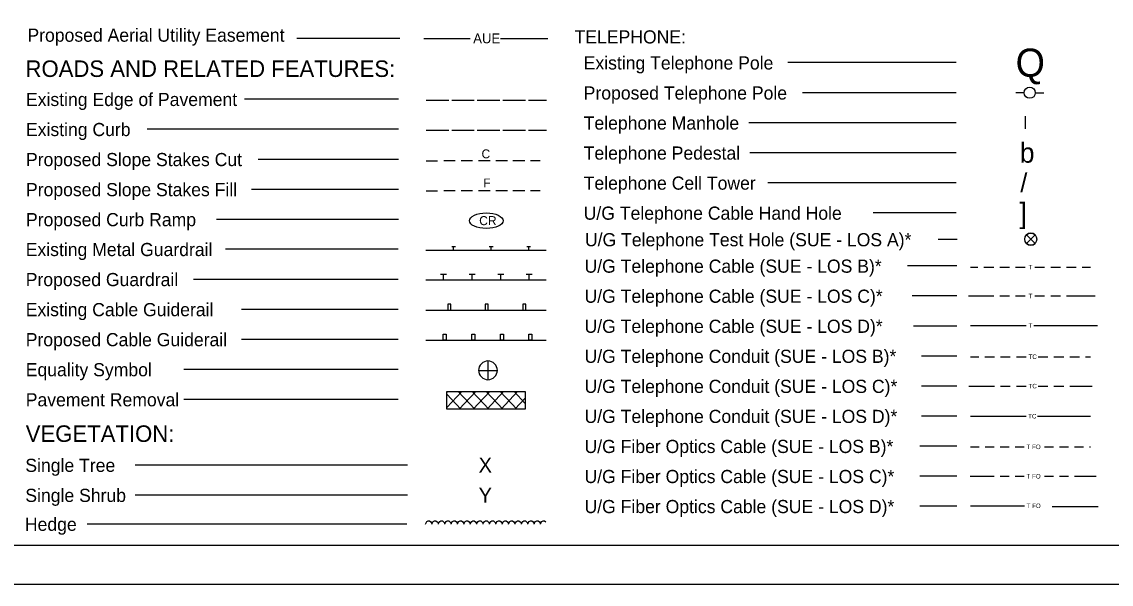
# Model space of a CAD drawing. Extents: x 885291.5 to 885334, y 651348 to 651383.7.
# Drawn here: x 885305.76 to 885323.88, y 651348.02 to 651357.38 of the extents above; entities that cross this region are included whole.
import ezdxf

# ---------------------------------------------------------------- set-up
doc = ezdxf.new("R2010")
doc.units = 0
for name, color, linetype in [('Default', 7, 'Continuous'), ('Prop WCC CELL', 7, 'Continuous'), ('Sheet Symbology CELL', 7, 'Continuous'), ('Stewart Plot Border Xerox6279 and LJ5000', 7, 'Continuous')]:
    doc.layers.add(name, color=color, linetype=linetype)

msp = doc.modelspace()

# ---------------------------------------------------------------- linework, layer by layer
at = {"layer": 'Default'}
for points in [[(885322.613, 651353.833), (885322.471, 651353.692), (885322.542, 651353.763), (885322.471, 651353.833), (885322.613, 651353.692)], [(885322.471, 651353.833), (885322.542, 651353.763), (885322.613, 651353.833)], [(885322.613, 651353.692), (885322.542, 651353.763), (885322.471, 651353.692)]]:
    msp.add_lwpolyline(points, dxfattribs=at)
msp.add_circle((885322.542, 651353.763), 0.0999, dxfattribs=at)
for start, end in [(45, 135), (225, 315)]:
    msp.add_arc((885322.542, 651353.763), 0.0999, start, end, dxfattribs=at)
at = {"layer": 'Prop WCC CELL'}
msp.add_ellipse((885313.486, 651354.07), major_axis=(0.28, 0), ratio=0.462467, dxfattribs=at)
at = {"layer": 'Sheet Symbology CELL'}
for p, q in [((885312.048, 651357.104), (885310.336, 651357.104)), ((885312.448, 651357.104), (885312.532, 651357.104)), ((885312.532, 651357.104), (885313.22, 651357.104)), ((885313.72, 651357.104), (885314.407, 651357.104)), ((885314.407, 651357.104), (885314.511, 651357.104)), ((885321.299, 651356.7), (885318.502, 651356.7)), ((885312.024, 651356.091), (885309.465, 651356.091)), ((885312.487, 651356.077), (885312.862, 651356.077)), ((885312.912, 651356.077), (885313.287, 651356.077)), ((885313.337, 651356.077), (885313.712, 651356.077)), ((885313.762, 651356.077), (885314.137, 651356.077)), ((885314.187, 651356.077), (885314.487, 651356.077)), ((885321.299, 651356.2), (885318.747, 651356.2)), ((885322.431, 651356.2), (885322.291, 651356.2)), ((885322.619, 651356.2), (885322.759, 651356.2)), ((885312.024, 651355.591), (885307.845, 651355.591)), ((885312.487, 651355.577), (885312.862, 651355.577)), ((885312.912, 651355.577), (885313.287, 651355.577)), ((885313.337, 651355.577), (885313.712, 651355.577)), ((885313.762, 651355.577), (885314.137, 651355.577)), ((885314.187, 651355.577), (885314.487, 651355.577)), ((885321.299, 651355.7), (885317.852, 651355.7)), ((885321.299, 651355.2), (885317.87, 651355.2)), ((885312.024, 651355.091), (885309.694, 651355.091)), ((885312.487, 651355.065), (885312.677, 651355.065)), ((885312.969, 651355.065), (885312.781, 651355.065)), ((885313.257, 651355.065), (885313.067, 651355.065)), ((885313.551, 651355.065), (885313.356, 651355.065)), ((885313.837, 651355.065), (885313.643, 651355.065)), ((885314.126, 651355.065), (885313.929, 651355.065)), ((885314.383, 651355.065), (885314.223, 651355.065)), ((885321.299, 651354.7), (885318.168, 651354.7)), ((885312.024, 651354.591), (885309.58, 651354.591)), ((885312.487, 651354.565), (885312.677, 651354.565)), ((885312.969, 651354.565), (885312.781, 651354.565)), ((885313.257, 651354.565), (885313.067, 651354.565)), ((885313.551, 651354.565), (885313.356, 651354.565)), ((885313.837, 651354.565), (885313.643, 651354.565)), ((885314.126, 651354.565), (885313.929, 651354.565)), ((885314.383, 651354.565), (885314.223, 651354.565)), ((885312.024, 651354.091), (885309, 651354.091)), ((885321.299, 651354.2), (885319.923, 651354.2)), ((885321.319, 651353.758), (885321.003, 651353.758)), ((885312.02, 651353.594), (885309.149, 651353.594)), ((885312.483, 651353.58), (885314.483, 651353.58)), ((885312.911, 651353.642), (885312.974, 651353.642)), ((885312.943, 651353.58), (885312.943, 651353.642)), ((885313.536, 651353.642), (885313.599, 651353.642)), ((885313.568, 651353.58), (885313.568, 651353.642)), ((885314.161, 651353.642), (885314.224, 651353.642)), ((885314.193, 651353.58), (885314.193, 651353.642)), ((885312.726, 651353.179), (885312.826, 651353.179)), ((885312.776, 651353.08), (885312.776, 651353.179)), ((885313.201, 651353.179), (885313.301, 651353.179)), ((885313.251, 651353.08), (885313.251, 651353.179)), ((885313.676, 651353.179), (885313.776, 651353.179)), ((885313.726, 651353.08), (885313.726, 651353.179)), ((885314.151, 651353.179), (885314.251, 651353.179)), ((885314.201, 651353.08), (885314.201, 651353.179)), ((885321.312, 651353.317), (885320.493, 651353.317)), ((885321.538, 651353.297), (885321.663, 651353.297)), ((885321.763, 651353.297), (885321.926, 651353.297)), ((885322.026, 651353.297), (885322.188, 651353.297)), ((885322.288, 651353.297), (885322.451, 651353.297)), ((885322.611, 651353.297), (885322.773, 651353.297)), ((885322.873, 651353.297), (885323.036, 651353.297)), ((885323.136, 651353.297), (885323.298, 651353.297)), ((885323.398, 651353.297), (885323.538, 651353.297)), ((885312.02, 651353.094), (885308.614, 651353.094)), ((885314.483, 651353.08), (885312.483, 651353.08)), ((885321.312, 651352.817), (885320.572, 651352.817)), ((885321.506, 651352.817), (885321.926, 651352.817)), ((885322.026, 651352.817), (885322.188, 651352.817)), ((885322.288, 651352.817), (885322.451, 651352.817)), ((885322.611, 651352.817), (885322.773, 651352.817)), ((885322.873, 651352.817), (885323.036, 651352.817)), ((885323.136, 651352.817), (885323.612, 651352.817)), ((885312.02, 651352.594), (885309.412, 651352.594)), ((885312.483, 651352.58), (885314.483, 651352.58)), ((885321.312, 651352.317), (885320.591, 651352.317)), ((885321.538, 651352.326), (885322.466, 651352.326)), ((885322.591, 651352.326), (885323.65, 651352.326)), ((885312.02, 651352.094), (885309.412, 651352.094)), ((885312.483, 651352.08), (885314.483, 651352.08)), ((885313.514, 651351.736), (885313.514, 651351.58)), ((885321.312, 651351.817), (885320.726, 651351.817)), ((885321.538, 651351.807), (885321.677, 651351.807)), ((885321.777, 651351.807), (885321.94, 651351.807)), ((885322.04, 651351.807), (885322.202, 651351.807)), ((885322.302, 651351.807), (885322.465, 651351.807)), ((885322.665, 651351.807), (885322.827, 651351.807)), ((885322.927, 651351.807), (885323.09, 651351.807)), ((885323.19, 651351.807), (885323.352, 651351.807)), ((885323.452, 651351.807), (885323.538, 651351.807)), ((885312.02, 651351.594), (885308.454, 651351.594)), ((885313.357, 651351.58), (885313.514, 651351.58)), ((885313.514, 651351.58), (885313.514, 651351.423)), ((885313.514, 651351.58), (885313.67, 651351.58)), ((885312.832, 651351.226), (885314.134, 651351.226)), ((885312.832, 651350.934), (885312.832, 651351.226)), ((885312.832, 651351.211), (885312.845, 651351.226)), ((885312.832, 651350.963), (885313.078, 651351.226)), ((885313.063, 651350.934), (885312.832, 651351.181)), ((885313.295, 651350.934), (885313.02, 651351.226)), ((885313.035, 651350.934), (885313.31, 651351.226)), ((885313.527, 651350.934), (885313.253, 651351.226)), ((885313.267, 651350.934), (885313.543, 651351.226)), ((885313.759, 651350.934), (885313.484, 651351.226)), ((885313.499, 651350.934), (885313.774, 651351.226)), ((885313.992, 651350.934), (885313.715, 651351.226)), ((885313.732, 651350.934), (885314.005, 651351.226)), ((885314.134, 651351.028), (885313.948, 651351.226)), ((885314.134, 651351.226), (885314.134, 651350.934)), ((885321.312, 651351.317), (885320.726, 651351.317)), ((885321.514, 651351.317), (885321.94, 651351.317)), ((885322.04, 651351.317), (885322.202, 651351.317)), ((885322.302, 651351.317), (885322.465, 651351.317)), ((885322.665, 651351.317), (885322.827, 651351.317)), ((885322.927, 651351.317), (885323.09, 651351.317)), ((885323.19, 651351.317), (885323.562, 651351.317)), ((885312.02, 651351.094), (885308.454, 651351.094)), ((885313.963, 651350.934), (885314.134, 651351.116)), ((885314.134, 651350.934), (885312.832, 651350.934)), ((885321.312, 651350.817), (885320.726, 651350.817)), ((885321.538, 651350.816), (885322.465, 651350.816)), ((885322.652, 651350.816), (885323.538, 651350.816)), ((885321.312, 651350.317), (885320.697, 651350.317)), ((885321.538, 651350.306), (885321.684, 651350.306)), ((885321.784, 651350.306), (885321.934, 651350.306)), ((885322.034, 651350.306), (885322.184, 651350.306)), ((885322.284, 651350.306), (885322.434, 651350.306)), ((885322.771, 651350.306), (885322.921, 651350.306)), ((885323.021, 651350.306), (885323.171, 651350.306)), ((885323.271, 651350.306), (885323.421, 651350.306)), ((885323.521, 651350.306), (885323.538, 651350.306)), ((885312.173, 651350.003), (885307.645, 651350.003)), ((885321.312, 651349.817), (885320.697, 651349.817)), ((885321.533, 651349.817), (885321.934, 651349.817)), ((885322.034, 651349.817), (885322.184, 651349.817)), ((885322.284, 651349.817), (885322.434, 651349.817)), ((885322.771, 651349.817), (885322.921, 651349.817)), ((885323.021, 651349.817), (885323.171, 651349.817)), ((885323.271, 651349.817), (885323.629, 651349.817)), ((885312.173, 651349.503), (885307.645, 651349.503)), ((885321.312, 651349.317), (885320.697, 651349.317)), ((885321.538, 651349.326), (885322.435, 651349.326)), ((885322.897, 651349.316), (885323.663, 651349.316)), ((885312.166, 651349.022), (885306.849, 651349.022)), ((885312.476, 651349.022), (885312.484, 651349.045)), ((885312.484, 651349.045), (885312.499, 651349.062)), ((885312.499, 651349.062), (885312.519, 651349.073)), ((885312.519, 651349.073), (885312.543, 651349.073)), ((885312.543, 651349.073), (885312.563, 651349.06)), ((885312.563, 651349.06), (885312.576, 651349.044)), ((885312.576, 651349.044), (885312.581, 651349.023)), ((885312.583, 651349.022), (885312.59, 651349.045)), ((885312.59, 651349.045), (885312.605, 651349.062)), ((885312.605, 651349.062), (885312.625, 651349.073)), ((885312.625, 651349.073), (885312.649, 651349.073)), ((885312.649, 651349.073), (885312.669, 651349.06)), ((885312.669, 651349.06), (885312.683, 651349.044)), ((885312.683, 651349.044), (885312.688, 651349.023)), ((885312.689, 651349.022), (885312.696, 651349.045)), ((885312.696, 651349.045), (885312.711, 651349.062)), ((885312.711, 651349.062), (885312.731, 651349.073)), ((885312.731, 651349.073), (885312.755, 651349.073)), ((885312.755, 651349.073), (885312.775, 651349.06)), ((885312.775, 651349.06), (885312.789, 651349.044)), ((885312.789, 651349.044), (885312.794, 651349.023)), ((885312.795, 651349.022), (885312.803, 651349.045)), ((885312.803, 651349.045), (885312.818, 651349.062)), ((885312.818, 651349.062), (885312.838, 651349.073)), ((885312.838, 651349.073), (885312.861, 651349.073)), ((885312.861, 651349.073), (885312.881, 651349.06)), ((885312.881, 651349.06), (885312.895, 651349.044)), ((885312.895, 651349.044), (885312.9, 651349.023)), ((885312.901, 651349.022), (885312.909, 651349.045)), ((885312.909, 651349.045), (885312.924, 651349.062)), ((885312.924, 651349.062), (885312.944, 651349.073)), ((885312.944, 651349.073), (885312.968, 651349.073)), ((885312.968, 651349.073), (885312.988, 651349.06)), ((885312.988, 651349.06), (885313.001, 651349.044)), ((885313.001, 651349.044), (885313.006, 651349.023)), ((885313.008, 651349.022), (885313.015, 651349.045)), ((885313.015, 651349.045), (885313.03, 651349.062)), ((885313.03, 651349.062), (885313.05, 651349.073)), ((885313.05, 651349.073), (885313.074, 651349.073)), ((885313.074, 651349.073), (885313.094, 651349.06)), ((885313.094, 651349.06), (885313.108, 651349.044)), ((885313.108, 651349.044), (885313.113, 651349.023)), ((885313.114, 651349.022), (885313.121, 651349.045)), ((885313.121, 651349.045), (885313.136, 651349.062)), ((885313.136, 651349.062), (885313.156, 651349.073)), ((885313.156, 651349.073), (885313.18, 651349.073)), ((885313.18, 651349.073), (885313.2, 651349.06)), ((885313.2, 651349.06), (885313.214, 651349.044)), ((885313.214, 651349.044), (885313.219, 651349.023)), ((885313.22, 651349.022), (885313.228, 651349.045)), ((885313.228, 651349.045), (885313.243, 651349.062)), ((885313.243, 651349.062), (885313.263, 651349.073)), ((885313.263, 651349.073), (885313.286, 651349.073)), ((885313.286, 651349.073), (885313.306, 651349.06)), ((885313.306, 651349.06), (885313.32, 651349.044)), ((885313.32, 651349.044), (885313.325, 651349.023)), ((885313.326, 651349.022), (885313.334, 651349.045)), ((885313.334, 651349.045), (885313.349, 651349.062)), ((885313.349, 651349.062), (885313.369, 651349.073)), ((885313.369, 651349.073), (885313.393, 651349.073)), ((885313.393, 651349.073), (885313.413, 651349.06)), ((885313.413, 651349.06), (885313.426, 651349.044)), ((885313.426, 651349.044), (885313.431, 651349.023)), ((885313.433, 651349.022), (885313.44, 651349.045)), ((885313.44, 651349.045), (885313.455, 651349.062)), ((885313.455, 651349.062), (885313.475, 651349.073)), ((885313.475, 651349.073), (885313.499, 651349.073)), ((885313.499, 651349.073), (885313.519, 651349.06)), ((885313.519, 651349.06), (885313.533, 651349.044)), ((885313.533, 651349.044), (885313.538, 651349.023)), ((885313.539, 651349.022), (885313.546, 651349.045)), ((885313.546, 651349.045), (885313.561, 651349.062)), ((885313.561, 651349.062), (885313.581, 651349.073)), ((885313.581, 651349.073), (885313.605, 651349.073)), ((885313.605, 651349.073), (885313.625, 651349.06)), ((885313.625, 651349.06), (885313.639, 651349.044)), ((885313.639, 651349.044), (885313.644, 651349.023)), ((885313.645, 651349.022), (885313.653, 651349.045)), ((885313.653, 651349.045), (885313.668, 651349.062)), ((885313.668, 651349.062), (885313.688, 651349.073)), ((885313.688, 651349.073), (885313.711, 651349.073)), ((885313.711, 651349.073), (885313.731, 651349.06)), ((885313.731, 651349.06), (885313.745, 651349.044)), ((885313.745, 651349.044), (885313.75, 651349.023)), ((885313.751, 651349.022), (885313.759, 651349.045)), ((885313.759, 651349.045), (885313.774, 651349.062)), ((885313.774, 651349.062), (885313.794, 651349.073)), ((885313.794, 651349.073), (885313.818, 651349.073)), ((885313.818, 651349.073), (885313.838, 651349.06)), ((885313.838, 651349.06), (885313.851, 651349.044)), ((885313.851, 651349.044), (885313.856, 651349.023)), ((885313.858, 651349.022), (885313.865, 651349.045)), ((885313.865, 651349.045), (885313.88, 651349.062)), ((885313.88, 651349.062), (885313.9, 651349.073)), ((885313.9, 651349.073), (885313.924, 651349.073)), ((885313.924, 651349.073), (885313.944, 651349.06)), ((885313.944, 651349.06), (885313.958, 651349.044)), ((885313.958, 651349.044), (885313.963, 651349.023)), ((885313.964, 651349.022), (885313.971, 651349.045)), ((885313.971, 651349.045), (885313.986, 651349.062)), ((885313.986, 651349.062), (885314.006, 651349.073)), ((885314.006, 651349.073), (885314.03, 651349.073)), ((885314.03, 651349.073), (885314.05, 651349.06)), ((885314.05, 651349.06), (885314.064, 651349.044)), ((885314.064, 651349.044), (885314.069, 651349.023)), ((885314.07, 651349.022), (885314.078, 651349.045)), ((885314.078, 651349.045), (885314.093, 651349.062)), ((885314.093, 651349.062), (885314.113, 651349.073)), ((885314.113, 651349.073), (885314.136, 651349.073)), ((885314.136, 651349.073), (885314.156, 651349.06)), ((885314.156, 651349.06), (885314.17, 651349.044)), ((885314.17, 651349.044), (885314.175, 651349.023)), ((885314.176, 651349.022), (885314.184, 651349.045)), ((885314.184, 651349.045), (885314.199, 651349.062)), ((885314.199, 651349.062), (885314.219, 651349.073)), ((885314.219, 651349.073), (885314.243, 651349.073)), ((885314.243, 651349.073), (885314.263, 651349.06)), ((885314.263, 651349.06), (885314.276, 651349.044)), ((885314.276, 651349.044), (885314.281, 651349.023)), ((885314.283, 651349.022), (885314.29, 651349.045)), ((885314.29, 651349.045), (885314.305, 651349.062)), ((885314.305, 651349.062), (885314.325, 651349.073)), ((885314.325, 651349.073), (885314.349, 651349.073)), ((885314.349, 651349.073), (885314.369, 651349.06)), ((885314.369, 651349.06), (885314.383, 651349.044)), ((885314.383, 651349.044), (885314.388, 651349.023)), ((885314.389, 651349.022), (885314.396, 651349.045)), ((885314.396, 651349.045), (885314.411, 651349.062)), ((885314.411, 651349.062), (885314.431, 651349.073)), ((885314.431, 651349.073), (885314.455, 651349.073)), ((885314.455, 651349.073), (885314.475, 651349.06)), ((885314.475, 651349.06), (885314.476, 651349.059))]:
    msp.add_line(p, q, dxfattribs=at)
for points in [[(885333.401, 651374.896), (885295.901, 651374.896), (885295.901, 651348.671), (885333.401, 651348.671)], [(885312.845, 651352.58), (885312.895, 651352.58), (885312.895, 651352.68), (885312.845, 651352.68)], [(885313.47, 651352.58), (885313.52, 651352.58), (885313.52, 651352.68), (885313.47, 651352.68)], [(885314.095, 651352.58), (885314.145, 651352.58), (885314.145, 651352.68), (885314.095, 651352.68)], [(885312.77, 651352.18), (885312.82, 651352.18), (885312.82, 651352.08), (885312.77, 651352.08)], [(885313.245, 651352.18), (885313.295, 651352.18), (885313.295, 651352.08), (885313.245, 651352.08)], [(885313.72, 651352.18), (885313.77, 651352.18), (885313.77, 651352.08), (885313.72, 651352.08)], [(885314.195, 651352.18), (885314.245, 651352.18), (885314.245, 651352.08), (885314.195, 651352.08)]]:
    msp.add_lwpolyline(points, close=True, dxfattribs=at)
msp.add_circle((885322.524, 651356.2), 0.0937, dxfattribs=at)
for start, end in [(89.9944, 179.9989), (359.9944, 89.9989), (179.9944, 269.9989), (269.9944, 359.9989)]:
    msp.add_arc((885313.514, 651351.58), 0.156, start, end, dxfattribs=at)
at = {"layer": 'Stewart Plot Border Xerox6279 and LJ5000'}
msp.add_lwpolyline([(885291.526, 651348.021), (885334.026, 651348.021), (885334.026, 651375.521), (885291.526, 651375.521)], close=True, dxfattribs=at)

# ---------------------------------------------------------------- texts
at = {"layer": 'Prop WCC CELL'}
msp.add_text('CR', height=0.15, dxfattribs=at).set_placement((885313.368, 651353.996))
at = {"layer": 'Sheet Symbology CELL'}
for s, height, p in [('Proposed Aerial Utility Easement', 0.21875, (885305.854, 651357.048)), ('AUE', 0.1637, (885313.268, 651357.022)), ('TELEPHONE:', 0.2188, (885314.954, 651357.019)), ('Existing Telephone Pole', 0.21875, (885315.106, 651356.586)), ('Q', 0.469, (885322.29, 651356.465)), ('ROADS AND RELATED FEATURES:', 0.275, (885305.822, 651356.462)), ('Proposed Telephone Pole', 0.21875, (885315.106, 651356.086)), ('Existing Edge of Pavement', 0.21875, (885305.83, 651355.978)), ('Telephone Manhole', 0.21875, (885315.106, 651355.586)), ('l', 0.206, (885322.421, 651355.597)), ('Existing Curb', 0.21875, (885305.83, 651355.478)), ('b', 0.33, (885322.359, 651355.035)), ('Proposed Slope Stakes Cut', 0.21875, (885305.83, 651354.978)), ('C', 0.148, (885313.407, 651355.108)), ('Telephone Pedestal', 0.21875, (885315.106, 651355.086)), ('Telephone Cell Tower', 0.21875, (885315.106, 651354.586)), ('/', 0.313, (885322.368, 651354.544)), ('Proposed Slope Stakes Fill', 0.21875, (885305.83, 651354.478)), ('F', 0.148, (885313.437, 651354.624)), ('U/G Telephone Cable Hand Hole', 0.21875, (885315.106, 651354.086)), (']', 0.337, (885322.355, 651354.031)), ('Proposed Curb Ramp', 0.21875, (885305.83, 651353.978)), ('U/G Telephone Test Hole (SUE - LOS A)*', 0.21875, (885315.127, 651353.644)), ('Existing Metal Guardrail', 0.21875, (885305.826, 651353.481)), ('U/G Telephone Cable (SUE - LOS B)*', 0.21875, (885315.12, 651353.204)), ('Proposed Guardrail', 0.21875, (885305.826, 651352.981)), ('T', 0.075, (885322.507, 651353.26)), ('U/G Telephone Cable (SUE - LOS C)*', 0.21875, (885315.12, 651352.704)), ('T', 0.075, (885322.507, 651352.78)), ('Existing Cable Guiderail', 0.21875, (885305.826, 651352.481)), ('U/G Telephone Cable (SUE - LOS D)*', 0.21875, (885315.12, 651352.204)), ('T', 0.075, (885322.505, 651352.289)), ('Proposed Cable Guiderail', 0.21875, (885305.826, 651351.981)), ('U/G Telephone Conduit (SUE - LOS B)*', 0.21875, (885315.12, 651351.704)), ('TC', 0.075, (885322.505, 651351.769)), ('Equality Symbol', 0.21875, (885305.826, 651351.481)), ('U/G Telephone Conduit (SUE - LOS C)*', 0.21875, (885315.12, 651351.204)), ('Pavement Removal', 0.21875, (885305.826, 651350.981)), ('TC', 0.075, (885322.505, 651351.28)), ('U/G Telephone Conduit (SUE - LOS D)*', 0.21875, (885315.12, 651350.704)), ('TC', 0.075, (885322.499, 651350.779)), ('VEGETATION:', 0.275, (885305.826, 651350.389)), ('U/G Fiber Optics Cable (SUE - LOS B)*', 0.21875, (885315.12, 651350.204)), ('T FO', 0.075, (885322.471, 651350.269)), ('Single Tree', 0.21875, (885305.819, 651349.89)), ('X', 0.25, (885313.358, 651349.878)), ('U/G Fiber Optics Cable (SUE - LOS C)*', 0.21875, (885315.12, 651349.704)), ('T FO', 0.075, (885322.471, 651349.78)), ('Single Shrub', 0.21875, (885305.819, 651349.39)), ('Y', 0.25, (885313.358, 651349.378)), ('U/G Fiber Optics Cable (SUE - LOS D)*', 0.21875, (885315.12, 651349.204)), ('T FO', 0.075, (885322.472, 651349.288)), ('Hedge', 0.2188, (885305.812, 651348.909))]:
    msp.add_text(s, height=height, dxfattribs=at).set_placement(p)

doc.saveas('drawing.dxf')
